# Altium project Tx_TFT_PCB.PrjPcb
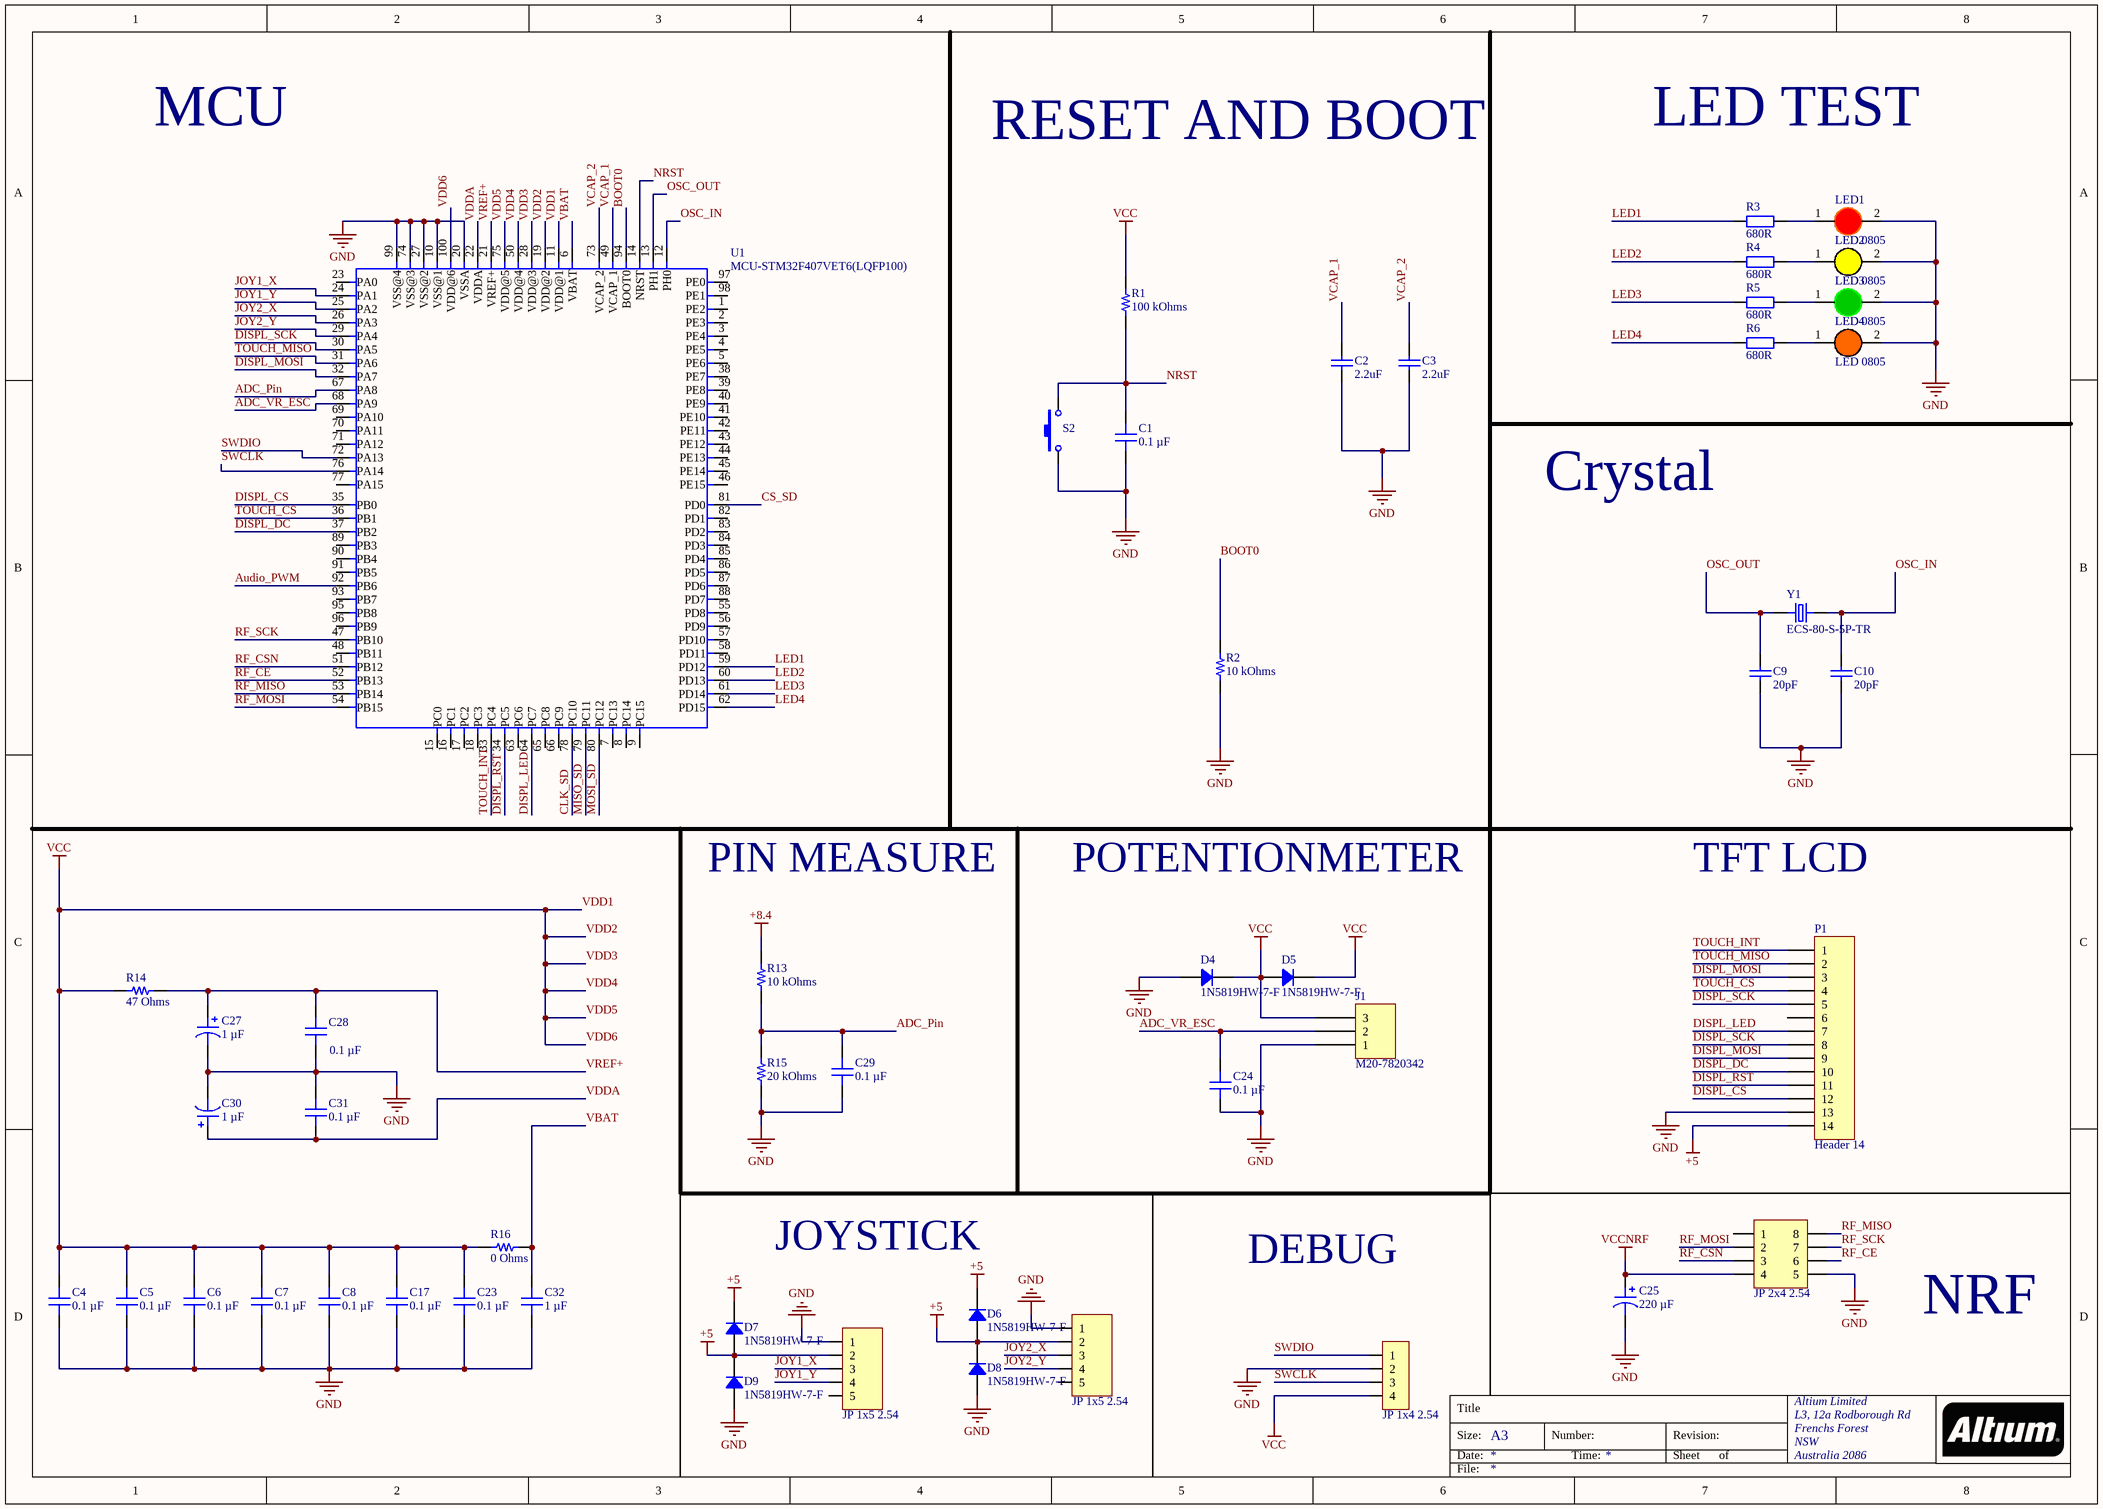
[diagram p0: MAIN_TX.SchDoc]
3 sheets, 90 parts. Net scope: global (net labels, ports and power ports of the same name join across sheets).
Board file: TX_PCB.PcbDoc
Sheets:
  MAIN_TX.SchDoc
  Audio.SchDoc
  Power_2.SchDoc

## Sheet MAIN_TX.SchDoc
size A3; Organization: Altium Limited; Address1: L3, 12a Rodborough Rd; Address2: Frenchs Forest; Address3: NSW; Address4: Australia 2086

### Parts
C1  0.1 µF  [CAP 0603_1608]
C2  2.2uF  [tu 0805]
C3  2.2uF  [tu 0805]
C4  0.1 µF  [CAP 0603_1608]
C5  Capacitance: 0.1 µF  [CAP 0603_1608]
C6  0.1 µF  [CAP 0603_1608]
C7  Capacitance: 0.1 µF  [CAP 0603_1608]
C8  Capacitance: 0.1 µF  [CAP 0603_1608]
C9  20pF  [tu 0805]
C10  20pF  [tu 0805]
C17  0.1 µF  [CAP 0603_1608]
C23  0.1 µF  [CAP 0603_1608]
C24  0.1 µF  [CAP 0603_1608]
C25  220 µF  [CAP ALSMD 6.6MM H6.1MM]
C27  1 µF  [CAP ALSMD 4.3MM H5.4MM]
C28  0.1 µF  [CAP 0603_1608]
C29  0.1 µF  [CAP 0603_1608]
C30  1 µF  [CAP ALSMD 4.3MM H5.4MM]
C31  0.1 µF  [CAP 0603_1608]
C32  1 µF  [CAP 0603_1608]
D4  1N5819HW-7-F  [SOD-123]
D5  1N5819HW-7-F  [SOD-123]
D6  1N5819HW-7-F  [SOD-123]
D7  1N5819HW-7-F  [SOD-123]
D8  1N5819HW-7-F  [SOD-123]
D9  1N5819HW-7-F  [SOD-123]
J1  M20-7820342  [HARWIN M20-7820345]
JP1  JP 1x4 2.54  [JP 1x4 DT]
JP2  JP 2x4 2.54  [JP 2x4 CT]
JP3  JP 1x5 2.54  [JP 1x5 DT]
JP4  JP 1x5 2.54  [JP 1x5 DT]
LED1  LED 0805  [LED-0805-Red]
LED2  LED 0805  [LED-0805-Yellow]
LED3  LED 0805  [LED-0805-Green]
LED4  LED 0805  [LED-0805-Orange]
P1  Header 14  [HDR1X14]
R1  100 kOhms  [RES 0603_1608]
R2  10 kOhms  [RES 0603_1608]
R3  680R  [tro smd 0603]
R4  680R  [tro smd 0603]
R5  680R  [tro smd 0603]
R6  680R  [tro smd 0603]
R13  10 kOhms  [RES 0603_1608]
R14  47 Ohms  [RES 0603_1608]
R15  20 kOhms  [RES 0603_1608]
R16  0 Ohms  [RES 0603_1608]
S2  SW-SMD  [SW-SMD]  (value not drawn)
U1  MCU-STM32F407VET6(LQFP100)  [LQFP100-0.5-13.8X13.8MM]
Y1  ECS-80-S-5P-TR  [XTAL_ECS-80-S-5P-TR]

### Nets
+5: D6.1 D6.2 D7.1 D7.2 D8.2 D9.2 JP3.2 JP4.2 P1.14
+8.4: R13.1
GND: C1.1 C2.1 C3.1 C4.1 C5.1 C6.1 C7.1 C8.1 C9.2 C10.2 C17.1 C23.1 C24.1 C25.2 C27.2 C28.1 C29.1 C30.2 C31.2 C32.1 D4.1 D8.1 D9.1 J1.1 JP1.2 JP2.5 JP3.1 JP4.1 LED1.2(K) LED2.2(K) LED3.2(K) LED4.2(K) P1.13 R2.2 R15.1 S2.1 U1.10(VSS@1) U1.20(VSSA) U1.27(VSS@2) U1.74(VSS@3) U1.99(VSS@4)
VCCNRF: C25.1 JP2.4
VDD1: C4.2 C5.2 C6.2 C7.2 C8.2 C17.2 C23.2 D4.2 D5.1 D5.2 J1.3 JP1.4 R1.2 R14.1 R16.1 U1.11(VDD@1) U1.19(VDD@2) U1.28(VDD@3) U1.50(VDD@4) U1.75(VDD@5) U1.100(VDD@6)  [also labelled VCC, VDD2, VDD3, VDD4, VDD5, VDD6]
ADC_Pin: C29.2 R13.2 R15.2 U1.67(PA8)
ADC_VR_ESC: C24.2 J1.2 U1.68(PA9)
Audio_PWM: U1.92(PB6)
BOOT0: R2.1 U1.94(BOOT0)
CLK_SD: U1.78(PC10)
CS_SD: U1.81(PD0)
DISPL_CS: P1.12 U1.35(PB0)
DISPL_DC: P1.10 U1.37(PB2)
DISPL_LED: P1.7 U1.64(PC7)
DISPL_MOSI: P1.3 P1.9 U1.32(PA7)
DISPL_RST: P1.11 U1.34(PC5)
DISPL_SCK: P1.5 P1.8 U1.30(PA5)
JOY1_X: JP3.3 U1.24(PA1)
JOY1_Y: JP3.4 U1.25(PA2)
JOY2_X: JP4.3 U1.26(PA3)
JOY2_Y: JP4.4 U1.29(PA4)
LED1: R3.1 U1.59(PD12)
LED2: R4.1 U1.60(PD13)
LED3: R5.1 U1.61(PD14)
LED4: R6.1 U1.62(PD15)
MISO_SD: U1.79(PC11)
MOSI_SD: U1.80(PC12)
NRST: C1.2 R1.1 S2.2 U1.14(NRST)
OSC_IN: C10.1 U1.12(PH0) Y1.2
OSC_OUT: C9.1 U1.13(PH1) Y1.1
RF_CE: JP2.6 U1.52(PB13)
RF_CSN: JP2.3 U1.51(PB12)
RF_MISO: JP2.8 U1.53(PB14)
RF_MOSI: JP2.2 U1.54(PB15)
RF_SCK: JP2.7 U1.47(PB10)
SWCLK: JP1.3 U1.76(PA14)
SWDIO: JP1.1 U1.72(PA13)
TOUCH_CS: P1.4 U1.36(PB1)
TOUCH_INT: P1.1 U1.33(PC4)
TOUCH_MISO: P1.2 U1.31(PA6)
VBAT: C32.2 R16.2 U1.6(VBAT)
VCAP_1: C2.2 U1.49(VCAP_1)
VCAP_2: C3.2 U1.73(VCAP_2)
VDDA: C30.1 C31.1 U1.22(VDDA)
VREF+: C27.1 C28.2 R14.2 U1.21(VREF+)
NetLED1_1: LED1.1(A) R3.2
NetLED2_1: LED2.1(A) R4.2
NetLED3_1: LED3.1(A) R5.2
NetLED4_1: LED4.1(A) R6.2

Not connected (* = marked no-connect by the designer): JP2 1; JP3 5; JP4 5; P1 6; U1 1(PE2) 2(PE3) 3(PE4) 4(PE5) 5(PE6) 7(PC13) 8(PC14) 9(PC15) 15(PC0) 16(PC1) 17(PC2) 18(PC3) 23(PA0) 38(PE7) 39(PE8) 40(PE9) 41(PE10) 42(PE11) 43(PE12) 44(PE13) 45(PE14) 46(PE15) 48(PB11) 55(PD8) 56(PD9) 57(PD10) 58(PD11) 63(PC6) 65(PC8) 66(PC9) 69(PA10) 70(PA11) 71(PA12) 77(PA15) 82(PD1) 83(PD2) 84(PD3) 85(PD4) 86(PD5) 87(PD6) 88(PD7) 89(PB3) 90(PB4) 91(PB5) 93(PB7) 95(PB8) 96(PB9) 97(PE0) 98(PE1)

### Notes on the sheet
- MCU
- RESET AND BOOT
- LED TEST
- Crystal
- PIN MEASURE
- POTENTIONMETER
- TFT LCD
- JOYSTICK
- DEBUG
- NRF

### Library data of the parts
C1 C4-C8 C17 C23 C28 C31 = C0603C104M8RAC7867: CAP CER 0.1UF 10V X7R 0603; manufacturer: KEMET; Tolerance: ±20%
C2 C3 = Tu 0805 225 25V 10%: Dán; Don_Vi: Con; So_Chan: 2; Ten_Linh_Kien: Tụ 0805 225-2.2uF 25V 10%; Ma_Hang: MH007483
C9 C10 = Tu 0805 20pF 50V 10%: Dán; Don_Vi: Con; Ten_Linh_Kien: Tụ 0805 20P 10% 50V; So_Chan: 2; Ma_Hang: MH004558
C24 C29 = VJ0603Y104KXQCW1BC: CAP CER 0.1UF 10V X7R 0603; manufacturer: Vishay Vitramon; Tolerance: ±10%
C25 = UCM1A221MCL1GS: CAP ALUM 220UF 20% 10V SMD; manufacturer: Nichicon; Impedance: 260 mOhms; Lifetime @ Temp.: 2000 Hrs @ 105°C; Polarization: Polar; Ripple Current @ High Frequency: 300 mA @ 100 kHz; Ripple Current @ Low Frequency: 150 mA @ 120 Hz; Surface Mount Land Size: 0.260" L x 0.260" W (6.60mm x 6.60mm)
C27 C30 = EEE-HD1H1R0R: CAP ALUM 1UF 20% 50V SMD; manufacturer: Panasonic Electronic Components; Impedance: 12 Ohms; Lifetime @ Temp.: 5000 Hrs @ 105°C; Polarization: Polar; Ripple Current @ High Frequency: 11.9 mA @ 10 kHz; Ripple Current @ Low Frequency: 7 mA @ 120 Hz; Surface Mount Land Size: 0.169" L x 0.169" W (4.30mm x 4.30mm)
C32 = C0603X105J8RAC7411: CAP CER 0603 1UF 10V X7R 5%; manufacturer: KEMET
D4-D9 = 1N5819HW-7-F: DIODE SCHOTTKY 40V 1A SOD123; Manufacturer: Diodes Incorporated; Capacitance @ Vr, F: 60pF @ 4V, 1MHz; Current - Reverse Leakage @ Vr: 1 mA @ 40 V; Speed: Fast Recovery =< 500ns, > 200mA (Io); Voltage - Forward (Vf) (Max) @ If: 450 mV @ 1 A
J1 = M20-7820342: CONN RCPT 3POS 0.1 GOLD PCB; Manufacturer: Harwin Inc.; Connector Type: Receptacle; Contact Length - Post: 0.118" (3.00mm); Current Rating (Amps): 3A; Mated Stacking Heights: 11.04mm, 12.63mm; Material Flammability Rating: UL94 V-0; Number of Positions: 3; Number of Positions Loaded: All; Pitch - Mating: 0.100" (2.54mm); Style: Board to Board or Cable
JP1 = JP 1x4 2.54 Duc Thang: Cắm; Ten_Linh_Kien: Jump Đơn Đực 2.54MM 1x40P Thẳng 11MM; Don_Vi: Con; Ma_Hang: MH000903
JP2 = JP 2x4 2.54 Cai Thang: Cắm; Ten_Linh_Kien: Jump Đôi Cái 2.54MM 2x20P Thẳng; Don_Vi: Con; Ma_Hang: MH008647
JP3 JP4 = JP 1x5 2.54 Duc Thang: Cắm; Ten_Linh_Kien: Jump Đơn Đực 2.54MM 1x40P Thẳng 11MM; Don_Vi: Con; Ma_Hang: MH000903
LED1 = LED 0805 Do: Dán; Don_Vi: Con; Ma_Hang: MH000897; Ten_Linh_Kien: LED 0805 Màu Đỏ (Red)
LED2 = LED 0805 Vang: Dán; Don_Vi: Con; Ma_Hang: MH002329; Ten_Linh_Kien: LED 0805 Màu Vàng ( Yellow)
LED3 = LED 0805 Xanh La: Dán; Don_Vi: Con; Ma_Hang: MH002326; Ten_Linh_Kien: LED 0805 Màu Xanh Lá (Green)
LED4 = LED 0805 Cam: Dán; Don_Vi: Con; Ma_Hang: MH002328; Ten_Linh_Kien: LED 0805 Màu Cam ( Orange)
P1 = Header 14: Header, 14-Pin
R1 = RN73H1JTTD1003B50: RES 100K OHM 0.1% 1/10W 0603; Manufacturer: KOA Speer Electronics, Inc.; Power (Watts): 0.1W, 1/10W; Temperature Coefficient: ±50ppm/°C
R2 R13 = CHP0603AFX-1002ELF: RESHIGHPOWERA 0603 10K 1% 1/3W T; Manufacturer: Bourns Inc.; Power (Watts): 0.333W, 1/3W; Temperature Coefficient: ±100ppm/°C
R3-R6 = Tro 0603 1% 680R: Dán; Don_Vi: Con; So_Chan: 2; Ten_Linh_Kien: Trở 0603 1% 680R; Ma_Hang: MH006336
R14 = CRT0603-FY-47R0ELF: RES SMD 47 OHM 1% 1/10W 0603; Manufacturer: Bourns Inc.; Power (Watts): 0.1W, 1/10W; Temperature Coefficient: ±25ppm/°C
R15 = RG1608P-203-B-T5: RES SMD 20K OHM 0.1% 1/10W 0603; Manufacturer: Susumu; Power (Watts): 0.1W, 1/10W; Temperature Coefficient: ±25ppm/°C
R16 = CR0603AJ/-000ELF: RES 0 OHM JUMPER 1/10W 0603; Manufacturer: Bourns Inc.; Power (Watts): 0.1W, 1/10W
S2 = SW-SMD: Switch
U1 = MCU-STM32F407VET6(LQFP100): ARMÂ® CortexÂ®-M4 STM32F4 Microcontroller IC 32-Bit Single-Core 168MHz 512KB (512K x 8) FLASH 100-LQFP (14x14); MF: STMicroelectronics
Y1 = ECS-80-S-5P-TR: CRYSTAL SMD

## Sheet Audio.SchDoc
size A4; Organization: Altium Limited; Address1: L3, 12a Rodborough Rd; Address2: Frenchs Forest; Address3: NSW; Address4: Australia 2086
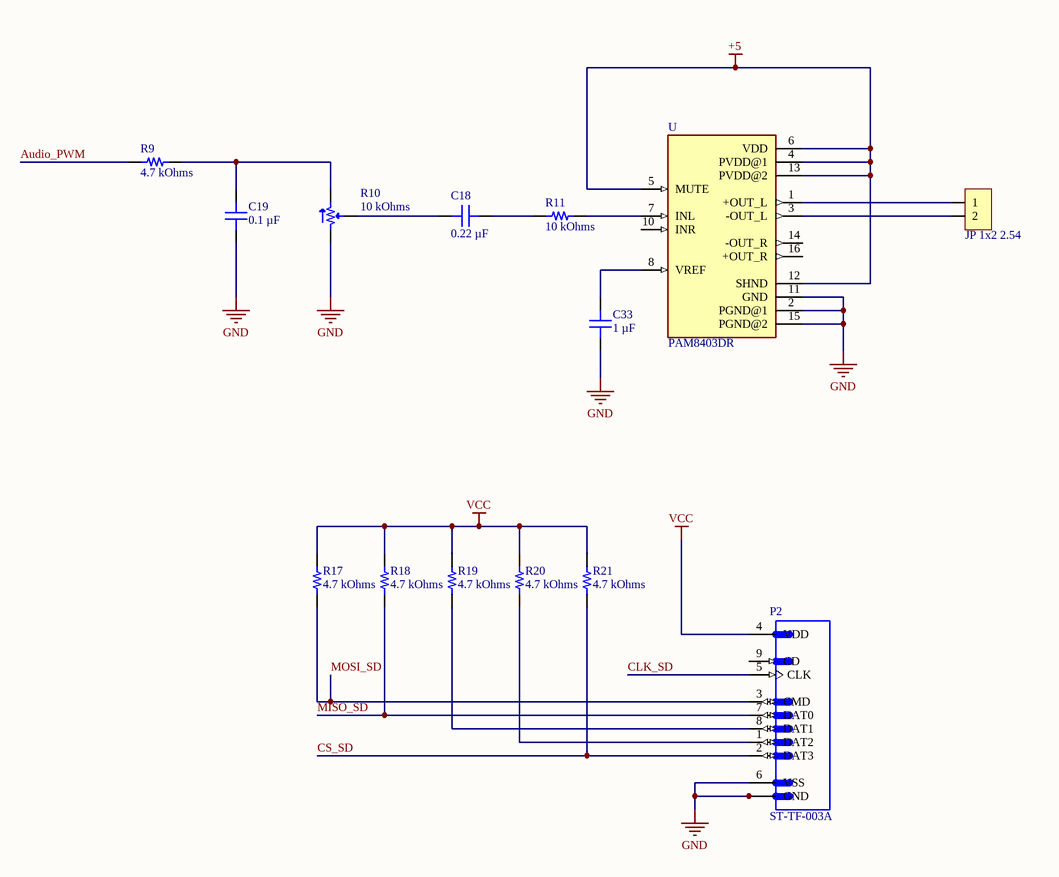
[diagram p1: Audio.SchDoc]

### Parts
C18  0.22 µF  [CAP 0603_1608]
C19  0.1 µF  [CAP 0603_1608]
C33  1 µF  [CAP 0603_1608]
JP5  JP 1x2 2.54  [JP 1x2 CT]
P2  ST-TF-003A  [SUNTECH_ST-TF-003A]
R9  4.7 kOhms  [RES 0603_1608]
R10  10 kOhms  [BOURNS TRIMPOT 3362P-1]
R11  10 kOhms  [RES 0603_1608]
R17  4.7 kOhms  [RES 0603_1608]
R18  4.7 kOhms  [RES 0603_1608]
R19  4.7 kOhms  [RES 0603_1608]
R20  4.7 kOhms  [RES 0603_1608]
R21  4.7 kOhms  [RES 0603_1608]
U  PAM8403DR  [SOIC127P605X150-16N]

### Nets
+5: U.4(PVDD@1) U.5(MUTE) U.6(VDD) U.12(SHND) U.13(PVDD@2)
GND: C19.1 C33.1 P2.6(VSS) P2.G1(GND) P2.G2(GND) P2.G3(GND) P2.G4(GND) R10.1 U.2(PGND@1) U.11(GND) U.15(PGND@2)
VCC: P2.4(VDD) R17.2 R18.2 R19.2 R20.2 R21.2  [project net VDD1]
Audio_PWM: R9.1
CLK_SD: P2.5(CLK)
CS_SD: P2.2(DAT3) R21.1
MISO_SD: P2.7(DAT0) R18.1
MOSI_SD: P2.3(CMD) R17.1
NetC18_1: C18.1 R11.1
NetC18_2: C18.2 R10.2
NetC19_2: C19.2 R9.2 R10.3
NetC33_2: C33.2 U.8(VREF)
NetJP5_1: JP5.1 U.1(+OUT_L)
NetJP5_2: JP5.2 U.3(-OUT_L)
NetP2_1: P2.1(DAT2) R20.1
NetP2_8: P2.8(DAT1) R19.1
NetR11_2: R11.2 U.7(INL)

Not connected (* = marked no-connect by the designer): P2 9(CD); U 10(INR) 14(-OUT_R) 16(+OUT_R)

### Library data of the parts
C18 = KAM15AR71A224KT: CAP CER 0.22UF 10V X7R 0603; manufacturer: KYOCERA AVX; Tolerance: ±10%
C19 = CL10F104ZB8NNNC: CAP CER 0.1UF 50V Y5V 0603; manufacturer: Samsung Electro-Mechanics; Temperature Coefficient: Y5V (F); Tolerance: -20%, +80%
C33 = UMK107ABJ105KAHT: CAP CER 1UF 50V X5R 0603; manufacturer: Taiyo Yuden; Tolerance: ±10%
JP5 = JP 1x2 2.54 Cai Thang: Cắm; Ten_Linh_Kien: Jump Đơn Cái 2.54MM 1x20P Thẳng; Don_Vi: Con; Ma_Hang: MH004006
P2 = ST-TF-003A: Micro SD Card Socket
R9 R17-R21 = RK73H1JTTD4701D: RES 4.7K OHM 0.5% 1/10W 0603; Manufacturer: KOA Speer Electronics, Inc.; Power (Watts): 0.1W, 1/10W; Temperature Coefficient: ±100ppm/°C
R10 = 3362P-1-103LF: TRIMMER 10K OHM 0.5W PC PIN TOP; Manufacturer: Bourns Inc.; Adjustment Type: Top Adjustment; Number of Turns: 1; Power (Watts): 0.5W, 1/2W; Resistive Material: Cermet; Temperature Coefficient: ±100ppm/°C; Tolerance: ±10%
R11 = RT0603DRE0710KL: RES SMD 10K OHM 0.5% 1/10W 0603; Manufacturer: Yageo; Power (Watts): 0.1W, 1/10W; Temperature Coefficient: ±50ppm/°C
U = PAM8403DR: Amplifier IC 2-Channel _Stereo_ Class D 16-SOP; MF: Diodes Inc.

## Sheet Power_2.SchDoc
size A4; Organization: Altium Limited; Address1: L3, 12a Rodborough Rd; Address2: Frenchs Forest; Address3: NSW; Address4: Australia 2086
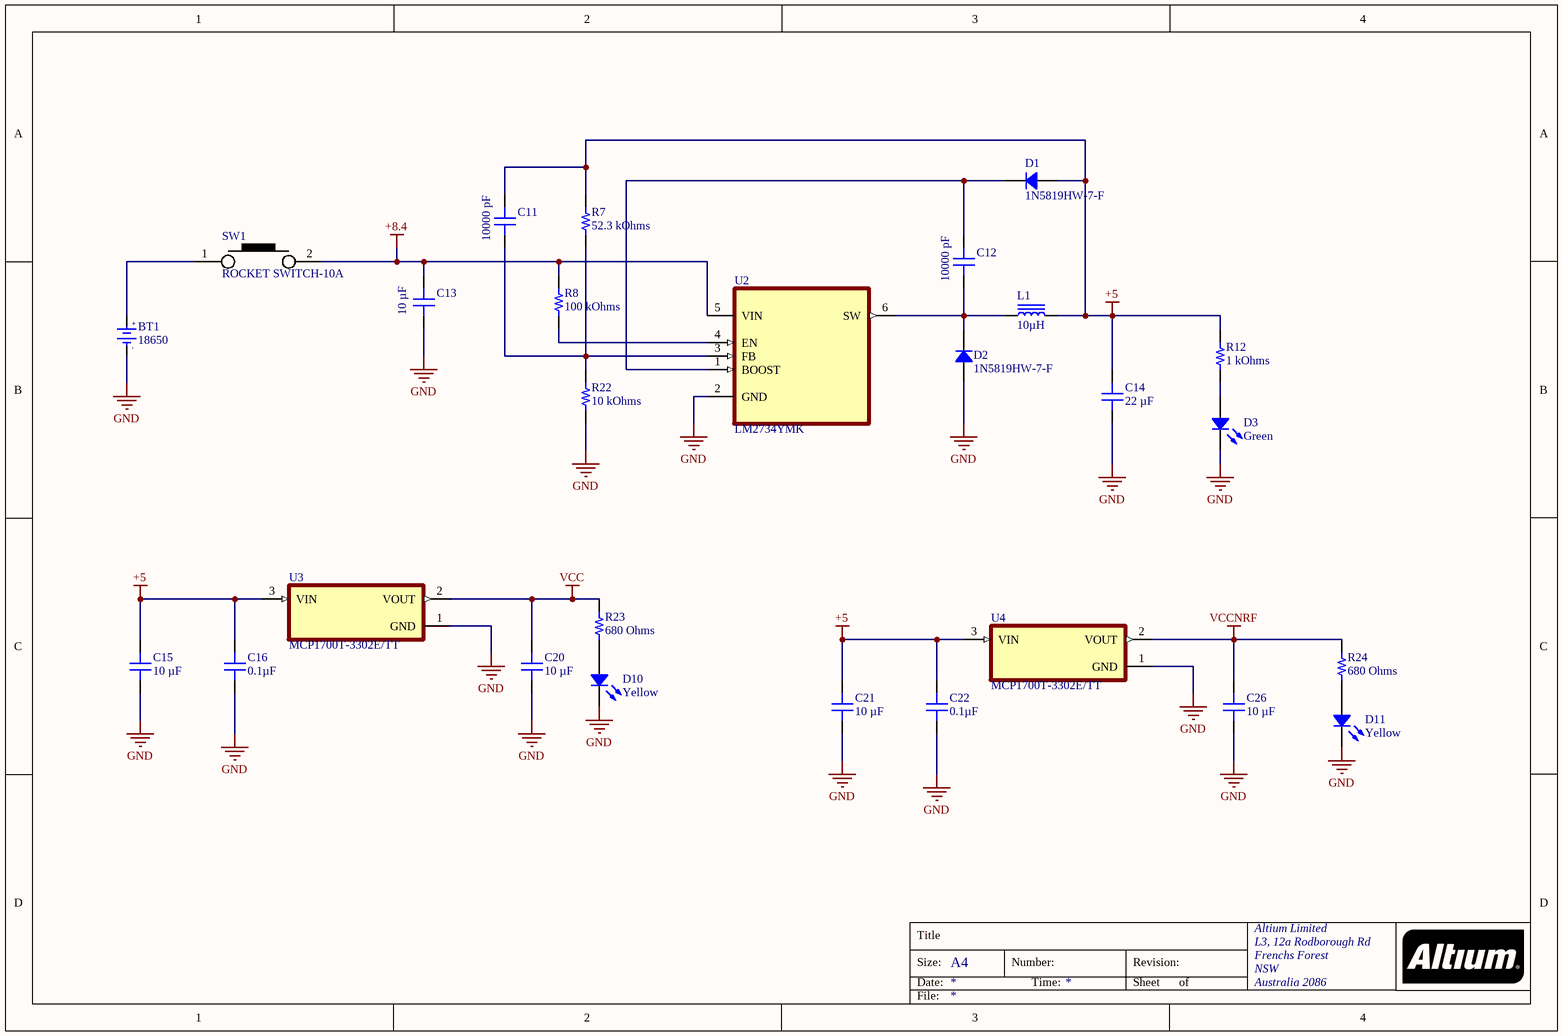
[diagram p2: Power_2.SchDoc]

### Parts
BT1  18650  [DE PIN 18650 X2]
C11  10000 pF  [CAP 0603_1608]
C12  10000 pF  [CAP 0603_1608]
C13  10 µF  [CAP 0805_2012]
C14  22 µF  [CAP 0805_2012]
C15  10 µF  [CAP 0805_2012]
C16  0.1µF  [CAP 0603_1608]
C20  10 µF  [CAP 0805_2012]
C21  10 µF  [CAP 0805_2012]
C22  0.1µF  [CAP 0603_1608]
C26  10 µF  [CAP 0805_2012]
D1  1N5819HW-7-F  [SOD-123]
D2  1N5819HW-7-F  [SOD-123]
D3  Green  [LED 0402_1005 GREEN]
D10  Yellow  [LED 0603_1608 YELLOW]
D11  Yellow  [LED 0603_1608 YELLOW]
L1  10µH  [TDK SLF7032]
R7  52.3 kOhms  [RES 0603_1608]
R8  100 kOhms  [RES 0603_1608]
R12  1 kOhms  [RES 0603_1608]
R22  10 kOhms  [RES 0603_1608]
R23  680 Ohms  [RES 0603_1608]
R24  680 Ohms  [RES 0603_1608]
SW1  ROCKET SWITCH-10A  [SW_2ARS_TH]
U2  LM2734YMK  [SOT95P285X100-6N]
U3  MCP1700T-3302E/TT  [SOT95P237X112-3N]
U4  MCP1700T-3302E/TT  [SOT95P237X112-3N]

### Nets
+5: C11.2 C14.2 C15.2 C16.2 C21.2 C22.2 D1.1 L1.2 R7.2 R12.2 U3.3(VIN) U4.3(VIN)
+8.4: C13.2 R8.2 SW1.2 U2.5(VIN)
GND: BT1.2(GND) C13.1 C14.1 C15.1 C16.1 C20.1 C21.1 C22.1 C26.1 D2.1 D3.2 D10.2 D11.2 R22.1 U2.2(GND) U3.1(GND) U4.1(GND)
VCC: C20.2 R23.2 U3.2(VOUT)  [project net VDD1]
VCCNRF: C26.2 R24.2 U4.2(VOUT)
NetBT1_1: BT1.1(+3V) SW1.1
NetC11_1: C11.1 R7.1 R22.2 U2.3(FB)
NetC12_1: C12.1 D2.2 L1.1 U2.6(SW)
NetC12_2: C12.2 D1.2 U2.1(BOOST)
NetD3_1: D3.1 R12.1
NetD10_1: D10.1 R23.1
NetD11_1: D11.1 R24.1
NetR8_1: R8.1 U2.4(EN)

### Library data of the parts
BT1 = De Pin 18650 x2: Ten: Hộp Đế Pin 18650 Hàn Mạch DP 18650-HM-02; Ma_Hang: MH010812
C11 C12 = C0603C103K4RECAUTO: CAP CER 0603 10NF 16V X7R 10%; manufacturer: KEMET
C13 = CL21X106KAYNNNE: CAP CER 10UF 25V X6S 0805; manufacturer: Samsung Electro-Mechanics; Tolerance: ±10%
C14 = CL21A226KQQNNNE: CAP CER 22UF 6.3V X5R 0805; manufacturer: Samsung Electro-Mechanics; Tolerance: ±10%
C15 C20 C21 C26 = C2012X6S1C106K125AC: CAP CER 10UF 16V X6S 0805; manufacturer: TDK Corporation; Tolerance: ±10%
C16 C22 = 0603YC104K4T4A: CAP CER 0.1UF 16V X7R 0603; manufacturer: AVX Corporation; Tolerance: ±10%
D1 D2 = 1N5819HW-7-F: as D4 on sheet MAIN_TX
D3 = QBLP595-AG15-2897: LED GREEN CLEAR 0402 SMD; Manufacturer: QT Brightek (QTB); Configuration: Standard; Current - Test: 5mA; Lens Color: Colorless; Lens Size: 0.70mm x 0.50mm; Lens Style: Rectangle with Flat Top; Millicandela Rating: 16.5mcd; Viewing Angle: 140°; Voltage - Forward (Vf) (Typ): 1.9V; Wavelength - Dominant: 570nm
D10 D11 = IN-S63AT5Y: LED YELLOW CLEAR 0603 SMD; Manufacturer: Inolux; Configuration: Standard; Current - Test: 5mA; Lens Size: 1.15mm x 0.80mm; Lens Style: Rectangle with Flat Top; Millicandela Rating: 35mcd; Viewing Angle: 120°; Voltage - Forward (Vf) (Typ): 2V; Wavelength - Dominant: 589nm; Wavelength - Peak: 593nm
L1 = SLF7032T-100M1R4-2PF: FIXED IND 10UH 1.4A 63.6 MOHM; Manufacturer: TDK Corporation; DC Resistance (DCR): 63.6mOhm Max; Inductance Frequency - Test: 100kHz; Material - Core: Ferrite; Shielding: Shielded; Tolerance: ±20%; Type: Wirewound
R7 = ERA-3AEB5232V: RES SMD 52.3KOHM 0.1% 1/10W 0603; Manufacturer: Panasonic Electronic Components; Power (Watts): 0.1W, 1/10W; Temperature Coefficient: ±25ppm/°C
R8 = RCA0603100KJNEA: RES SMD 100K OHM 5% 1/10W 0603; Manufacturer: Vishay Dale; Power (Watts): 0.1W, 1/10W; Temperature Coefficient: ±200ppm/°C
R12 = RN73R1JTTD1001B25: RES 1K OHM 0.1% 1/10W 0603; Manufacturer: KOA Speer Electronics, Inc.; Power (Watts): 0.1W, 1/10W; Temperature Coefficient: ±25ppm/°C
R22 = TNPU060310K0BZEN00: RES SMD 10K OHM 0.1% 1/10W 0603; Manufacturer: Vishay Dale; Power (Watts): 0.1W, 1/10W; Temperature Coefficient: ±5ppm/°C
R23 R24 = RT0603CRD07680RL: RES SMD 680 OHM 0.25% 1/10W 0603; Manufacturer: Yageo; Power (Watts): 0.1W, 1/10W; Temperature Coefficient: ±25ppm/°C
SW1 = SW1_10A-SRB23A2BBBNN-TH: Rocker Switch SPDT 10A (AC) 125V Panel Mount, Snap-In; Manufacturer: ITT C&K; Alternate Part Number-1: NA
U2 = LM2734YMK: Buck Switching Regulator IC Positive Adjustable 0.8V 1 Output 1A SOT-23-6 Thin, TSOT-23-6; MF: Texas Instruments
U3 U4 = MCP1700T-3302E/TT: Linear Voltage Regulator IC 1 Output 250mA SOT-23-3; MF: Microchip

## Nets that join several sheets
+5: MAIN_TX (9 pins), Audio (5 pins), Power_2 (12 pins)
+8.4: MAIN_TX (R13.1), Power_2 (C13.2 R8.2 SW1.2 U2.5)
GND: MAIN_TX (41 pins), Audio (11 pins), Power_2 (17 pins)
VCCNRF: MAIN_TX (C25.1 JP2.4), Power_2 (C26.2 R24.2 U4.2)
VDD1: MAIN_TX (21 pins), Audio (6 pins), Power_2 (C20.2 R23.2 U3.2)
Audio_PWM: MAIN_TX (U1.92), Audio (R9.1)
CLK_SD: MAIN_TX (U1.78), Audio (P2.5)
CS_SD: MAIN_TX (U1.81), Audio (P2.2 R21.1)
MISO_SD: MAIN_TX (U1.79), Audio (P2.7 R18.1)
MOSI_SD: MAIN_TX (U1.80), Audio (P2.3 R17.1)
